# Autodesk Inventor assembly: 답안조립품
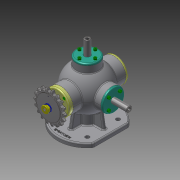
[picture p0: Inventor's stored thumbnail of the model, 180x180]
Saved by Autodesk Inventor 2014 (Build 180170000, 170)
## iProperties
Created: 2016-03
Part Number: 답안조립품
Document SubType Name: Assembly
Designer: SEC
Author: SEC
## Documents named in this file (17)
- C:\Documents and Settings\SEC\바탕 화면\360307V1021\답안조립품.iam
- C:\Documents and Settings\SEC\바탕 화면\360307V1021\본체.ipt
- C:\Documents and Settings\SEC\바탕 화면\360307V1021\본체커버.ipt
- C:\Documents and Settings\SEC\바탕 화면\360307V1021\뒤커버.ipt
- C:\Documents and Settings\SEC\바탕 화면\360307V1021\앞커버.ipt
- C:\Documents and Settings\SEC\바탕 화면\360307V1021\베어링- 6202.ipt
- C:\Documents and Settings\SEC\바탕 화면\360307V1021\오일실.ipt
- C:\Documents and Settings\SEC\바탕 화면\360307V1021\슬라이드 커버.ipt
- C:\Documents and Settings\SEC\바탕 화면\360307V1021\축.ipt
- C:\Documents and Settings\SEC\바탕 화면\360307V1021\슬라이드.ipt
- C:\Documents and Settings\SEC\바탕 화면\360307V1021\키 3 x 3 x 12.ipt
- C:\Documents and Settings\SEC\바탕 화면\360307V1021\스프로킷.ipt
- C:\Documents and Settings\SEC\바탕 화면\360307V1021\와셔 8x17.ipt
- C:\Documents and Settings\SEC\바탕 화면\360307V1021\너트-M8x1.ipt
- C:\Documents and Settings\SEC\바탕 화면\360307V1021\볼트 M4x0.7.ipt
- C:\Documents and Settings\SEC\바탕 화면\360307V1021\15 스프링.ipt
- C:\Documents and Settings\SEC\바탕 화면\360307V1021\16 스프링.ipt
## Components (19 placed, 3 different names)
1. M4x0.7x12:5
2. 15 스프링:1
3. 16 스프링:1
4. M4x0.7x12:3
5. M4x0.7x12:9
6. M4x0.7x12:10
7. M4x0.7x12:11
8. M4x0.7x12:1
9. M4x0.7x12:12
10. M4x0.7x12:13
11. M4x0.7x12:14
12. M4x0.7x12:4
13. M4x0.7x12:15
14. M4x0.7x12:16
15. M4x0.7x12:17
16. M4x0.7x12:2
17. M4x0.7x12:18
18. M4x0.7x12:19
19. M4x0.7x12:20
